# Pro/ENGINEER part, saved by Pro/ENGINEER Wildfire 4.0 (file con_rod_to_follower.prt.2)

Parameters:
  METRIC = "NO"

Other parameters: PITCH, DRILL_POINT_ANGLE, DRILL_DEPTH, DRILL_DIAMETER, THREAD_DIAMETER, THREADS_PER_INCH, THREAD_DEPTH, THREAD_LENGTH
